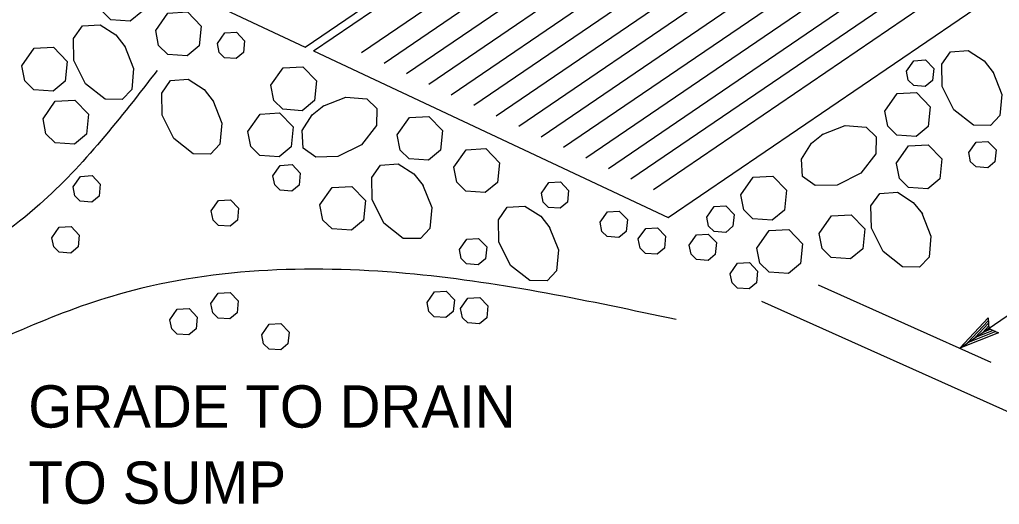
# Model space of a CAD drawing. Extents: x 6709491 to 6710959, y 1869789 to 1870763.
# Drawn here: x 6709827.6 to 6709966.5, y 1870113.2 to 1870181.9 of the extents above; entities that cross this region are included whole.
import ezdxf

# ---------------------------------------------------------------- set-up
doc = ezdxf.new("R2010")
doc.units = 0
for name, color, linetype in [('56 Stg 3 Anno', 7, 'Continuous'), ('57 Undefined', 7, 'Continuous'), ('60 Nongeo Data', 7, 'Continuous')]:
    doc.layers.add(name, color=color, linetype=linetype)

msp = doc.modelspace()

# ---------------------------------------------------------------- linework, layer by layer
at = {"layer": '56 Stg 3 Anno'}
for p, q in [((6709960.88, 1870135.33), (6710117.29, 1870242.71)), ((6709940.78, 1870144.34), (6709965.26, 1870133.36)), ((6709932.78, 1870142.01), (6709989.45, 1870116.59)), ((6709960.88, 1870135.33), (6709964.91, 1870139.64)), ((6709964.91, 1870139.64), (6709964.91, 1870139.64)), ((6709964.91, 1870139.64), (6709965, 1870138.15)), ((6709961.98, 1870136.08), (6709964.92, 1870139.23)), ((6709963.07, 1870136.83), (6709964.97, 1870138.86)), ((6709964.16, 1870137.58), (6709964.97, 1870138.44)), ((6709965, 1870138.15), (6709966.36, 1870137.53)), ((6709966.36, 1870137.53), (6709960.88, 1870135.33)), ((6709965.99, 1870137.69), (6709961.97, 1870136.08)), ((6709965.61, 1870137.85), (6709963.07, 1870136.83)), ((6709965.29, 1870138.03), (6709964.16, 1870137.58)), ((6709966.36, 1870137.53), (6709966.36, 1870137.53)), ((6709960.88, 1870135.33), (6709960.88, 1870135.33))]:
    msp.add_line(p, q, dxfattribs=at)
at = {"layer": '60 Nongeo Data'}
for p, q in [((6709868.08, 1870178.04), (6709946.01, 1870231.15)), ((6709869.25, 1870177.49), (6709947.18, 1870230.6)), ((6709876.08, 1870177.26), (6709948.76, 1870226.79)), ((6709879.26, 1870175.77), (6709951.94, 1870225.3)), ((6709882.44, 1870174.27), (6709955.12, 1870223.81)), ((6709885.62, 1870172.78), (6709958.3, 1870222.31)), ((6709888.8, 1870171.28), (6709961.48, 1870220.82)), ((6709891.99, 1870169.79), (6709964.66, 1870219.33)), ((6709895.17, 1870168.3), (6709967.84, 1870217.83)), ((6709898.35, 1870166.8), (6709971.02, 1870216.34)), ((6709901.53, 1870165.31), (6709974.21, 1870214.84)), ((6709904.71, 1870163.82), (6709977.39, 1870213.35)), ((6709907.89, 1870162.32), (6709980.57, 1870211.86)), ((6709911.07, 1870160.83), (6709983.75, 1870210.36)), ((6709914.25, 1870159.33), (6709986.93, 1870208.87)), ((6709917.44, 1870157.84), (6709990.11, 1870207.37)), ((6709919.56, 1870153.86), (6709997.49, 1870206.98)), ((6709817.77, 1870201.66), (6709868.08, 1870178.04)), ((6709869.25, 1870177.49), (6709919.56, 1870153.86))]:
    msp.add_line(p, q, dxfattribs=at)
for points in [[(6709838.84, 1870185.31), (6709840.58, 1870187.79), (6709843.36, 1870187.94), (6709845.29, 1870185.94), (6709845.01, 1870183.14), (6709843.29, 1870181.71), (6709840.55, 1870181.91), (6709839.26, 1870183.16), (6709838.84, 1870185.31)], [(6709846.89, 1870180.39), (6709848.63, 1870182.86), (6709851.41, 1870183.02), (6709853.34, 1870181.02), (6709853.06, 1870178.21), (6709851.34, 1870176.79), (6709848.6, 1870176.99), (6709847.31, 1870178.24), (6709846.89, 1870180.39)], [(6709842.46, 1870178.26), (6709843.75, 1870175.01), (6709843.49, 1870172.02), (6709842.14, 1870170.6), (6709839.72, 1870170.64), (6709836.96, 1870172.8), (6709835.29, 1870176.13), (6709835.24, 1870179.27), (6709836.5, 1870181.04), (6709839, 1870181.21), (6709841.23, 1870179.78), (6709842.54, 1870178.13)], [(6709855.63, 1870178.56), (6709856.68, 1870180.05), (6709858.34, 1870180.14), (6709859.5, 1870178.94), (6709859.33, 1870177.26), (6709858.3, 1870176.4), (6709856.66, 1870176.52), (6709855.88, 1870177.27), (6709855.63, 1870178.56)], [(6709827.91, 1870175.38), (6709829.65, 1870177.86), (6709832.42, 1870178.01), (6709834.36, 1870176.01), (6709834.08, 1870173.21), (6709832.36, 1870171.78), (6709829.62, 1870171.98), (6709828.33, 1870173.23), (6709827.91, 1870175.38)], [(6709965.54, 1870174.58), (6709966.83, 1870171.33), (6709966.57, 1870168.34), (6709965.22, 1870166.92), (6709962.8, 1870166.96), (6709960.04, 1870169.12), (6709958.38, 1870172.45), (6709958.32, 1870175.59), (6709959.58, 1870177.36), (6709962.08, 1870177.53), (6709964.32, 1870176.09), (6709965.63, 1870174.45)], [(6709953.32, 1870174.62), (6709954.36, 1870176.1), (6709956.03, 1870176.2), (6709957.19, 1870175), (6709957.02, 1870173.31), (6709955.99, 1870172.46), (6709954.35, 1870172.58), (6709953.57, 1870173.33), (6709953.32, 1870174.62)], [(6709863.22, 1870172.61), (6709864.96, 1870175.09), (6709867.74, 1870175.25), (6709869.67, 1870173.24), (6709869.39, 1870170.44), (6709867.67, 1870169.01), (6709864.93, 1870169.21), (6709863.64, 1870170.46), (6709863.22, 1870172.61)], [(6709854.97, 1870170.51), (6709856.26, 1870167.26), (6709856, 1870164.27), (6709854.65, 1870162.85), (6709852.22, 1870162.89), (6709849.47, 1870165.05), (6709847.8, 1870168.38), (6709847.74, 1870171.52), (6709849, 1870173.29), (6709851.5, 1870173.46), (6709853.74, 1870172.02), (6709855.05, 1870170.38)], [(6709950.25, 1870168.95), (6709951.99, 1870171.43), (6709954.76, 1870171.58), (6709956.69, 1870169.58), (6709956.41, 1870166.78), (6709954.7, 1870165.35), (6709951.96, 1870165.55), (6709950.67, 1870166.8), (6709950.25, 1870168.95)], [(6709830.92, 1870167.87), (6709832.66, 1870170.35), (6709835.43, 1870170.5), (6709837.36, 1870168.5), (6709837.08, 1870165.7), (6709835.37, 1870164.27), (6709832.63, 1870164.47), (6709831.34, 1870165.72), (6709830.92, 1870167.87)], [(6709870.59, 1870169.66), (6709873.84, 1870170.95), (6709876.83, 1870170.7), (6709878.26, 1870169.34), (6709878.21, 1870166.92), (6709876.05, 1870164.16), (6709872.72, 1870162.5), (6709869.58, 1870162.44), (6709867.81, 1870163.7), (6709867.65, 1870166.2), (6709869.08, 1870168.44), (6709870.72, 1870169.75)], [(6709859.95, 1870166.07), (6709861.69, 1870168.54), (6709864.46, 1870168.7), (6709866.39, 1870166.7), (6709866.11, 1870163.89), (6709864.4, 1870162.47), (6709861.66, 1870162.66), (6709860.37, 1870163.92), (6709859.95, 1870166.07)], [(6709881.11, 1870165.58), (6709882.85, 1870168.06), (6709885.63, 1870168.21), (6709887.56, 1870166.21), (6709887.28, 1870163.41), (6709885.56, 1870161.98), (6709882.82, 1870162.18), (6709881.53, 1870163.43), (6709881.11, 1870165.58)], [(6709941.37, 1870165.63), (6709944.62, 1870166.92), (6709947.61, 1870166.66), (6709949.03, 1870165.31), (6709948.98, 1870162.88), (6709946.83, 1870160.13), (6709943.5, 1870158.46), (6709940.36, 1870158.41), (6709938.59, 1870159.66), (6709938.42, 1870162.16), (6709939.86, 1870164.4), (6709941.5, 1870165.71)], [(6709962.16, 1870163.08), (6709963.2, 1870164.56), (6709964.87, 1870164.65), (6709966.03, 1870163.45), (6709965.86, 1870161.77), (6709964.83, 1870160.91), (6709963.19, 1870161.03), (6709962.41, 1870161.78), (6709962.16, 1870163.07)], [(6709889.16, 1870161.01), (6709890.9, 1870163.48), (6709893.68, 1870163.64), (6709895.61, 1870161.64), (6709895.33, 1870158.83), (6709893.61, 1870157.41), (6709890.87, 1870157.61), (6709889.58, 1870158.86), (6709889.16, 1870161.01)], [(6709951.88, 1870161.54), (6709953.62, 1870164.02), (6709956.4, 1870164.18), (6709958.33, 1870162.18), (6709958.05, 1870159.37), (6709956.34, 1870157.94), (6709953.59, 1870158.14), (6709952.31, 1870159.39), (6709951.89, 1870161.54)], [(6709863.52, 1870159.78), (6709864.56, 1870161.26), (6709866.23, 1870161.36), (6709867.38, 1870160.16), (6709867.22, 1870158.47), (6709866.19, 1870157.62), (6709864.54, 1870157.74), (6709863.77, 1870158.49), (6709863.52, 1870159.78)], [(6709884.73, 1870158.53), (6709886.02, 1870155.28), (6709885.76, 1870152.29), (6709884.41, 1870150.87), (6709881.98, 1870150.91), (6709879.23, 1870153.07), (6709877.56, 1870156.4), (6709877.51, 1870159.54), (6709878.76, 1870161.31), (6709881.27, 1870161.48), (6709883.5, 1870160.04), (6709884.81, 1870158.4)], [(6709835.17, 1870158.22), (6709836.21, 1870159.7), (6709837.88, 1870159.8), (6709839.04, 1870158.6), (6709838.87, 1870156.91), (6709837.84, 1870156.06), (6709836.2, 1870156.18), (6709835.42, 1870156.93), (6709835.17, 1870158.22)], [(6709901.57, 1870157.34), (6709902.61, 1870158.82), (6709904.28, 1870158.92), (6709905.43, 1870157.71), (6709905.27, 1870156.03), (6709904.24, 1870155.18), (6709902.59, 1870155.29), (6709901.82, 1870156.04), (6709901.57, 1870157.34)], [(6709929.84, 1870157.1), (6709931.58, 1870159.57), (6709934.36, 1870159.73), (6709936.29, 1870157.73), (6709936.01, 1870154.92), (6709934.29, 1870153.5), (6709931.55, 1870153.7), (6709930.26, 1870154.95), (6709929.84, 1870157.1)], [(6709870.18, 1870155.65), (6709871.92, 1870158.12), (6709874.69, 1870158.28), (6709876.62, 1870156.28), (6709876.34, 1870153.48), (6709874.63, 1870152.05), (6709871.89, 1870152.25), (6709870.6, 1870153.5), (6709870.18, 1870155.65)], [(6709854.77, 1870154.79), (6709855.81, 1870156.27), (6709857.48, 1870156.37), (6709858.64, 1870155.17), (6709858.47, 1870153.48), (6709857.44, 1870152.63), (6709855.8, 1870152.75), (6709855.02, 1870153.5), (6709854.77, 1870154.79)], [(6709955.5, 1870154.5), (6709956.79, 1870151.24), (6709956.54, 1870148.25), (6709955.18, 1870146.83), (6709952.76, 1870146.88), (6709950, 1870149.03), (6709948.34, 1870152.37), (6709948.28, 1870155.51), (6709949.54, 1870157.27), (6709952.04, 1870157.44), (6709954.28, 1870156.01), (6709955.59, 1870154.37)], [(6709902.69, 1870152.54), (6709903.98, 1870149.29), (6709903.72, 1870146.3), (6709902.37, 1870144.88), (6709899.95, 1870144.92), (6709897.19, 1870147.08), (6709895.53, 1870150.41), (6709895.47, 1870153.55), (6709896.73, 1870155.32), (6709899.23, 1870155.49), (6709901.47, 1870154.05), (6709902.78, 1870152.41)], [(6709909.88, 1870153.19), (6709910.92, 1870154.68), (6709912.59, 1870154.77), (6709913.75, 1870153.57), (6709913.58, 1870151.89), (6709912.55, 1870151.03), (6709910.9, 1870151.15), (6709910.13, 1870151.9), (6709909.88, 1870153.19)], [(6709925.02, 1870153.92), (6709926.06, 1870155.41), (6709927.73, 1870155.5), (6709928.88, 1870154.3), (6709928.72, 1870152.62), (6709927.69, 1870151.76), (6709926.04, 1870151.88), (6709925.27, 1870152.63), (6709925.02, 1870153.92)], [(6709940.95, 1870151.61), (6709942.69, 1870154.09), (6709945.47, 1870154.25), (6709947.4, 1870152.25), (6709947.12, 1870149.44), (6709945.4, 1870148.01), (6709942.66, 1870148.21), (6709941.37, 1870149.46), (6709940.95, 1870151.61)], [(6709832.18, 1870150.99), (6709833.22, 1870152.48), (6709834.89, 1870152.57), (6709836.04, 1870151.37), (6709835.88, 1870149.69), (6709834.85, 1870148.83), (6709833.2, 1870148.95), (6709832.43, 1870149.7), (6709832.18, 1870150.99)], [(6709915.3, 1870150.82), (6709916.35, 1870152.3), (6709918.01, 1870152.4), (6709919.17, 1870151.2), (6709919, 1870149.51), (6709917.97, 1870148.66), (6709916.33, 1870148.78), (6709915.56, 1870149.53), (6709915.3, 1870150.82)], [(6709932.13, 1870149.52), (6709933.87, 1870152), (6709936.65, 1870152.16), (6709938.58, 1870150.15), (6709938.3, 1870147.35), (6709936.58, 1870145.92), (6709933.84, 1870146.12), (6709932.55, 1870147.37), (6709932.13, 1870149.52)], [(6709889.95, 1870149.32), (6709890.99, 1870150.81), (6709892.66, 1870150.9), (6709893.81, 1870149.7), (6709893.65, 1870148.02), (6709892.62, 1870147.16), (6709890.97, 1870147.28), (6709890.2, 1870148.03), (6709889.95, 1870149.32)], [(6709922.52, 1870149.94), (6709923.57, 1870151.42), (6709925.23, 1870151.52), (6709926.39, 1870150.31), (6709926.22, 1870148.63), (6709925.2, 1870147.78), (6709923.55, 1870147.89), (6709922.78, 1870148.65), (6709922.52, 1870149.94)], [(6709928.34, 1870145.9), (6709929.38, 1870147.39), (6709931.05, 1870147.48), (6709932.21, 1870146.28), (6709932.04, 1870144.6), (6709931.01, 1870143.74), (6709929.36, 1870143.86), (6709928.59, 1870144.61), (6709928.34, 1870145.9)], [(6709854.72, 1870141.66), (6709855.76, 1870143.14), (6709857.43, 1870143.24), (6709858.59, 1870142.03), (6709858.42, 1870140.35), (6709857.39, 1870139.5), (6709855.74, 1870139.61), (6709854.97, 1870140.37), (6709854.72, 1870141.66)], [(6709885.36, 1870141.83), (6709886.41, 1870143.32), (6709888.07, 1870143.41), (6709889.23, 1870142.21), (6709889.06, 1870140.53), (6709888.03, 1870139.67), (6709886.39, 1870139.79), (6709885.62, 1870140.54), (6709885.36, 1870141.83)], [(6709890.12, 1870140.95), (6709891.16, 1870142.44), (6709892.83, 1870142.53), (6709893.99, 1870141.33), (6709893.82, 1870139.65), (6709892.79, 1870138.79), (6709891.14, 1870138.91), (6709890.37, 1870139.66), (6709890.12, 1870140.95)], [(6709848.91, 1870139.37), (6709849.95, 1870140.85), (6709851.62, 1870140.95), (6709852.77, 1870139.74), (6709852.61, 1870138.06), (6709851.58, 1870137.21), (6709849.93, 1870137.32), (6709849.16, 1870138.08), (6709848.91, 1870139.37)], [(6709861.94, 1870137.25), (6709862.98, 1870138.74), (6709864.65, 1870138.83), (6709865.81, 1870137.63), (6709865.64, 1870135.95), (6709864.61, 1870135.09), (6709862.96, 1870135.21), (6709862.19, 1870135.96), (6709861.94, 1870137.25)]]:
    msp.add_lwpolyline(points, dxfattribs=at)
for points in [[(6709847.1, 1870174.73), (6709830.46, 1870155.75), (6709805.06, 1870139.39)], [(6709920.67, 1870139.39), (6709883.59, 1870145.82), (6709842.43, 1870143.19), (6709815.28, 1870132.09)]]:
    msp.add_spline(points, degree=3, dxfattribs=at)

# ---------------------------------------------------------------- texts
at = {"layer": '57 Undefined'}
for s, p in [('GRADE TO DRAIN ', (6709828.83, 1870124.07)), ('TO SUMP', (6709828.83, 1870113.27))]:
    msp.add_text(s, height=6, dxfattribs=at).set_placement(p)

doc.saveas('drawing.dxf')
